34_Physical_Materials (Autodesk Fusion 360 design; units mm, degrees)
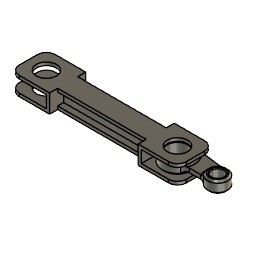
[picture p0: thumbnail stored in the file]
part number: 2026-07-17-16-29-27-626
part number: 2026-07-17-16-31-56-177
sketch "Sketch1" plane through (0, 0, 0) normal (0, 0, 1) x axis (1, 0, 0)
  line L1 (-50, 0) -> (50, 0)
  line L2 (53.125, 24.8039) -> (-45.3125, 37.2059)
  line L3 (-15.6307, -15) -> (30, -15)
  circle C1 centre (-50, 0) radius 37.5
  circle C2 centre (50, 0) radius 25
  circle C3 centre (-50, 0) radius 25
  circle C4 centre (50, 0) radius 15
  point P4 (0, 0)
  point P1 (0, 0)
  point P3 (-50, 0)
  point P5 (-50, 0)
  point P2 (50, 0)
  point P6 (50, 0)
  point P7 (-45.3125, 37.2059)
  point P8 (53.125, 24.8039)
  point P9 (30, -15)
  point P10 (-15.6307, -15)
  midpoint L1 P4
  coincident P1 P4
  horizontal L1
  coincident P3 P5
  coincident P2 P6
  coincident C1 P7
  coincident C2 P8
  tangent C2 L2
  coincident C2 P9
  coincident C1 P10
  horizontal L3
  tangent C1 L2
  concentric C1 C3
  concentric C2 C4
  dimension "d1" distance P2 P3 = 100
  dimension "d2" diameter C2 = 50
  dimension "d3" diameter C1 = 75
  dimension "d4" distance L1 L3 = 15
  dimension "d5" diameter C3 = 50
  dimension "d6" diameter C4 = 30
extrude "Extrude1" new body sketch "Sketch1" profile of C1 C2 L2 L3 C3 C4 distance 5
extrude "Extrude2" add sketch "Sketch1" profile of C1 C2 C3 C4 distance 15
fillet "Fillet1" radius 17.5
fillet "Fillet2" radius 5
chamfer "Chamfer1" distance 5
chamfer "Chamfer2" distance 2
sketch "Sketch1" plane through (0, 0, 0) normal (0, 1, 0) x axis (1, 0, 0)
  line L1 (-95, -15) -> (-5, -15)
  line L2 (-95, 15) -> (-95, -15)
  line L3 (-5, 15) -> (-95, 15)
  line L4 (-95, 0) -> (0, 0)
  line L5 (-103, -23) -> (-5, -23)
  line L6 (-103, 23) -> (-103, -23)
  line L7 (-5, 23) -> (-103, 23)
  line L8 (-5, -23) -> (-5, -15)
  line L9 (-5, 23) -> (-5, 15)
  point P7 (-95, 0)
  point P1 (0, 0)
  point P6 (0, 0)
  point P3 (-95, -15)
  point P4 (-95, 15)
  point P5 (-5, 15)
  horizontal L1
  perpendicular L1 L2
  perpendicular L2 L3
  midpoint L2 P7
  perpendicular L2 L4
  coincident P1 P6
  equal L1 L3
  perpendicular L5 L8
  perpendicular L7 L9
  dimension "d17" distance P3 P4 = 30
  dimension "d18" distance P6 P7 = 95
  dimension "d19" distance P4 P5 = 90
  dimension "d20" = -8
extrude "Extrude1" new body sketch "Sketch1" profile of L1 L2 L3 L6 L5 L7 L8 L9 distance 45
fillet "Fillet1" radius 22.5
sketch "Sketch2" plane through (0, 0, 23) normal (0, 0, 1) x axis (-1, 0, 0)
  line L1 (103, -45) -> (27.5, -45)
  line L2 (103, 45) -> (103, -45)
  line L3 (27.5, 45) -> (103, 45)
  line L4 (5, -22.5) -> (5, 22.5)
  arc A1 centre (27.5, -22.5) radius 22.5 clockwise from (27.5, -45) to (5, -22.5)
  arc A2 centre (27.5, 22.5) radius 22.5 clockwise from (5, 22.5) to (27.5, 45)
  circle C1 centre (50, 0) radius 25
extrude "Extrude2" cut sketch "Sketch2" profile of C1 no distance stored
sketch "Sketch3" plane through (-103, 0, 0) normal (-1, 0, 0) x axis (0, -1, 0)
  line L1 (-45, 23) -> (45, 23)
  line L2 (-45, -23) -> (-45, 23)
  line L3 (45, -23) -> (-45, -23)
  line L4 (45, 23) -> (45, -23)
  line L5 (0, 23) -> (0, 0)
  line L6 (-25, 23) -> (0, 23)
  line L7 (-25, 15) -> (-25, 23)
  line L8 (-10, 15) -> (-25, 15)
  line L9 (-10, 0) -> (-10, 15)
  line L10 (0, 0) -> (-10, 0)
  line L11 (-25, -15) -> (-25, -23)
  line L12 (-10, -15) -> (-25, -15)
  line L13 (-10, 0) -> (-10, -15)
  line L14 (10, 15) -> (25, 15)
  line L15 (10, 0) -> (10, 15)
  line L16 (25, 15) -> (25, 23)
  line L17 (10, 0) -> (10, -15)
  line L18 (10, -15) -> (25, -15)
  line L19 (25, -15) -> (25, -23)
  line L20 (25, 23) -> (0, 23)
  line L21 (45, 23) -> (-45, 23)
  line L22 (45, -23) -> (45, 23)
  line L23 (-45, 23) -> (-45, -23)
  line L24 (25, -23) -> (-25, -23)
  point P1 (0, 0)
  point P6 (0, 0)
  point P7 (0, 23)
  point P8 (-25, 23)
  point P12 (-25, -23)
  point P9 (-25, 15)
  point P13 (-25, -15)
  point P10 (-10, 15)
  point P14 (-10, -15)
  point P11 (-10, 0)
  point P15 (-10, 0)
  point P2 (45, 23)
  point P25 (-45, 23)
  point P3 (-45, 23)
  point P26 (45, 23)
  point P4 (-45, -23)
  point P27 (45, -23)
  point P5 (45, -23)
  point P28 (-45, -23)
  point P24 (0, 23)
  point P19 (25, 23)
  point P16 (25, 15)
  point P17 (10, 15)
  point P18 (10, 0)
  point P23 (25, -23)
  point P22 (25, -15)
  point P20 (10, -15)
  point P21 (10, 0)
  coincident P1 P6
  midpoint L1 P7
  coincident L1 P8
  perpendicular L6 L7
  perpendicular L7 L8
  perpendicular L6 L9
  perpendicular L5 L10
  symmetric P8 L10 P12
  symmetric P9 L10 P13
  symmetric P10 L10 P14
  symmetric P11 L10 P15
  symmetric P2 L5 P25
  symmetric P3 L5 P26
  symmetric P4 L5 P27
  symmetric P5 L5 P28
  symmetric P7 L5 P24
  symmetric L5 P8 P19
  symmetric L5 P9 P16
  symmetric L5 P10 P17
  symmetric L5 P11 P18
  symmetric L5 P12 P23
  symmetric L5 P13 P22
  symmetric L5 P14 P20
  symmetric L5 P15 P21
  dimension "d26" distance P6 P11 = 10
  dimension "d27" distance P8 P9 = 8
  dimension "d28" distance P9 P10 = 15
extrude "Extrude3" add sketch "Sketch3" profile of L1 L3 L6 L7 L8 L9 L11 L12 L13 L14 L15 L16 L17 L18 L19 L20 L21 L24 along normal blind 110
mirror "Mirror1" mirrorStitchTolerance 0.1
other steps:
create_component "CreateComponent1"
